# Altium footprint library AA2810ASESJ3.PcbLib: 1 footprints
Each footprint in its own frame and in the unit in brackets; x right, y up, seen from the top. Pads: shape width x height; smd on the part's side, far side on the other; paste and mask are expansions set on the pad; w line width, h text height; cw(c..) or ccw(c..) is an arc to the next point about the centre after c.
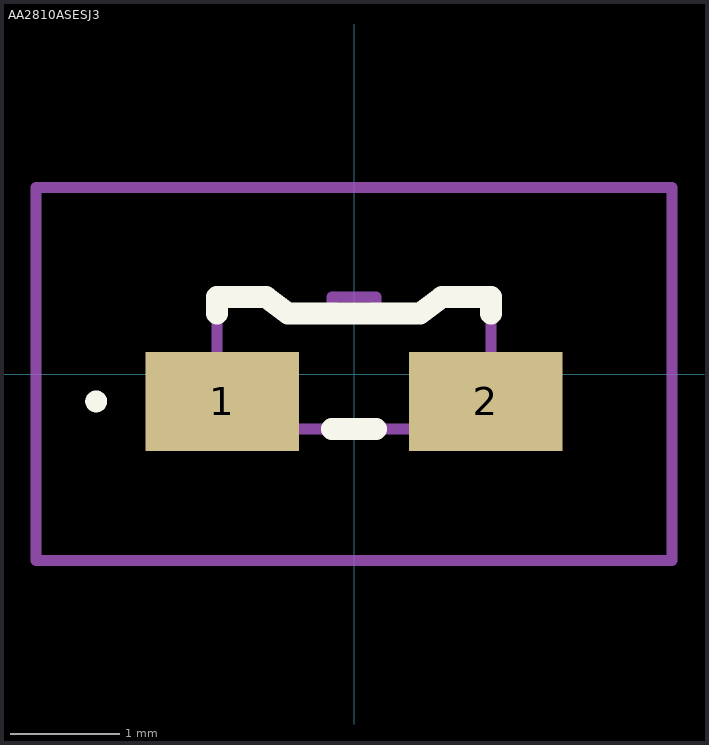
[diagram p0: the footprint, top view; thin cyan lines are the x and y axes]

## AA2810ASESJ3 [mm]
pads (2):
  rect 1.4x0.9 smd: 1(-1.2,-0.25) 2(1.2,-0.25)
Top Overlay:
  lines w0.1: -2.4,-0.25 -2.4,-0.25 ; -2.4,-0.25 ccw(c-2.35,-0.25) -2.3,-0.25 ; -2.4,-0.25 cw(c-2.35,-0.25) -2.3,-0.25 ; -2.3,-0.25 -2.3,-0.25
  lines w0.2: -1.25,0.55 -1.25,0.7 -0.8,0.7 -0.6,0.55 0.6,0.55 0.8,0.7 1.25,0.7 1.25,0.55 ; -0.2,-0.5 0.2,-0.5
Mechanical 15:
  lines w0.1: -1.25,-0.45 -1.4,-0.45 -1.4,-0.05 -1.25,-0.05 ; -0.2,0.55 -0.2,0.7 0.2,0.7 0.2,0.55 ; 1.25,-0.45 1.4,-0.45 1.4,-0.05 1.25,-0.05 ; 1.25,0.7 0.8,0.7 0.6,0.55 -0.6,0.55 -0.8,0.7 -1.25,0.7 -1.25,0.35 -1.25,-0.5 1.25,-0.5 1.25,0.7 ; 1.25,0.7 1.25,0.7
Mechanical 20:
  lines w0.1: -2.9,-1.7 2.9,-1.7 2.9,1.7 -2.9,1.7 -2.9,-1.7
